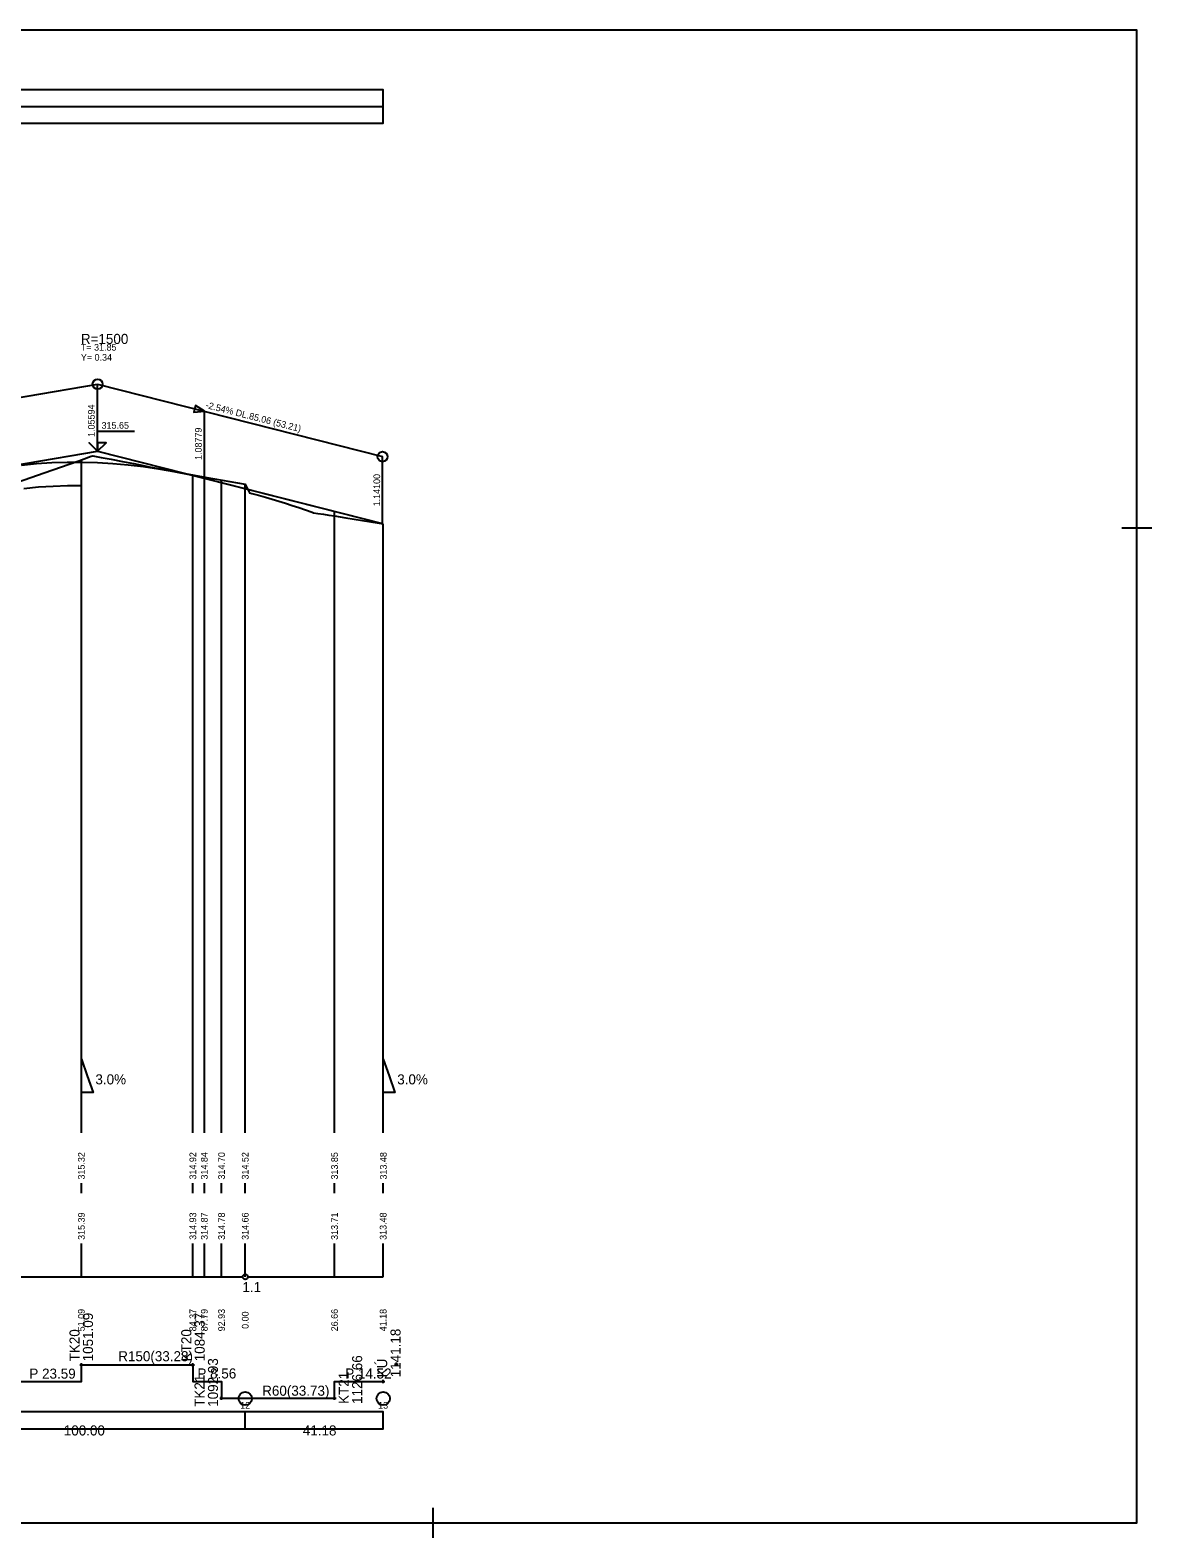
# Model space of a CAD drawing. Extents: x 1301 to 1448, y 183 to 228.
# Drawn here: x 1414.92 to 1448.4, y 182.54 to 227.54 of the extents above; entities that cross this region are included whole.
import ezdxf

# ---------------------------------------------------------------- set-up
doc = ezdxf.new("R2010")
doc.units = 0
for name, color, linetype in [('KOTA', 7, 'Continuous'), ('NOVY_STAV', 7, 'Continuous'), ('NS_OBLOUK', 7, 'Continuous'), ('REZY_PO', 7, 'Continuous'), ('SESTAVY_REZU_PO', 7, 'Continuous'), ('SKLONOVE_POMERY', 7, 'Continuous'), ('SMEROVE_POMERY', 7, 'Continuous'), ('SMEROVE_POMERY_KOD', 7, 'Continuous'), ('SVK_STAT', 7, 'Continuous'), ('TABULKY', 7, 'Continuous'), ('u_drenaz', 7, 'Continuous'), ('u_pricne_rezy', 7, 'Continuous'), ('x_formát_rám', 7, 'Continuous')]:
    doc.layers.add(name, color=color, linetype=linetype)

msp = doc.modelspace()

# ---------------------------------------------------------------- linework, layer by layer
at = {"layer": 'KOTA'}
for points in [[(1416.937, 214.971), (1416.687, 215.221), (1416.937, 214.971), (1416.937, 215.571), (1418.037, 215.571)], [(1416.937, 215.221), (1416.937, 214.971), (1417.187, 215.221), (1416.937, 215.221)], [(1416.937, 214.971), (1417.187, 215.221), (1416.937, 215.221)], [(1416.937, 214.971), (1416.937, 214.971)]]:
    msp.add_lwpolyline(points, dxfattribs=at)
at = {"layer": 'NOVY_STAV'}
for points in [[(1408.521, 215.539), (1416.937, 216.971)], [(1416.937, 214.971), (1416.937, 216.971)], [(1416.937, 216.971), (1425.443, 214.807)], [(1371.343, 199.496), (1372.956, 201.369), (1382.912, 202.588), (1387.709, 206.246), (1394.33, 206.448), (1402.893, 208.614), (1408.521, 213.539), (1416.937, 214.971), (1425.443, 212.807)], [(1425.443, 212.807), (1425.443, 214.807)], [(1414.662, 214.557), (1415.117, 214.6), (1415.572, 214.629), (1416.027, 214.644), (1416.482, 214.646), (1416.937, 214.633), (1417.392, 214.607), (1417.847, 214.567), (1418.302, 214.514), (1418.757, 214.446), (1419.212, 214.365), (1419.667, 214.27), (1420.121, 214.161), (1425.443, 212.807)]]:
    msp.add_lwpolyline(points, dxfattribs=at)
for centre in [(1416.937, 216.971), (1425.443, 214.807)]:
    msp.add_circle(centre, 0.15, dxfattribs=at)
at = {"layer": 'NS_OBLOUK'}
for points in [[(1419.806, 216.138), (1420.122, 216.161), (1419.855, 216.332), (1419.806, 216.138)], [(1420.122, 214.161), (1420.122, 216.161)]]:
    msp.add_lwpolyline(points, dxfattribs=at)
msp.add_lwpolyline([(1420.122, 216.161), (1419.855, 216.332), (1419.806, 216.138)], close=True, dxfattribs=at)
at = {"layer": 'REZY_PO'}
for points in [[(1414.343, 213.98), (1415.343, 214.328), (1416.343, 214.676), (1416.452, 214.714), (1416.452, 214.714), (1416.452, 214.714), (1416.749, 214.818), (1416.789, 214.833), (1417.046, 214.783), (1417.343, 214.728), (1417.676, 214.666), (1418.009, 214.607), (1418.019, 214.605), (1418.343, 214.534), (1418.525, 214.494), (1420.2, 214.181)], [(1420.2, 214.181), (1421.343, 213.984), (1421.343, 213.984), (1421.468, 213.728), (1421.543, 213.709), (1421.743, 213.656), (1421.943, 213.6), (1422.143, 213.541), (1422.343, 213.481), (1422.543, 213.418), (1422.743, 213.353), (1422.943, 213.286), (1423.143, 213.216), (1423.343, 213.145), (1423.383, 213.13), (1423.509, 213.114), (1423.676, 213.09), (1423.842, 213.065), (1424.009, 213.039), (1424.343, 212.985), (1425.343, 212.823), (1425.461, 212.804)]]:
    msp.add_lwpolyline(points, dxfattribs=at)
at = {"layer": 'SESTAVY_REZU_PO'}
for points in [[(1411.418, 190.326), (1421.268, 190.326)], [(1421.418, 190.326), (1425.461, 190.326)]]:
    msp.add_lwpolyline(points, dxfattribs=at)
msp.add_circle((1421.343, 190.326), 0.075, dxfattribs=at)
at = {"layer": 'SKLONOVE_POMERY'}
for points in [[(1416.452, 195.826), (1416.452, 196.826), (1416.452, 196.826), (1416.627, 196.326), (1416.802, 195.826), (1416.452, 195.826)], [(1425.461, 195.826), (1425.461, 196.826), (1425.461, 196.826), (1425.636, 196.326), (1425.811, 195.826), (1425.461, 195.826)]]:
    msp.add_lwpolyline(points, dxfattribs=at)
at = {"layer": 'SMEROVE_POMERY'}
msp.add_lwpolyline([(1414.092, 187.204), (1416.452, 187.204), (1416.452, 187.704), (1419.78, 187.704), (1419.78, 187.204), (1420.636, 187.204), (1420.636, 186.704), (1424.009, 186.704), (1424.009, 187.204), (1425.461, 187.204)], dxfattribs=at)
at = {"layer": 'SMEROVE_POMERY_KOD'}
for points in [[(1416.402, 187.704), (1416.502, 187.704)], [(1416.452, 187.654), (1416.452, 187.754)], [(1419.73, 187.704), (1419.83, 187.704)], [(1419.78, 187.654), (1419.78, 187.754)], [(1425.803, 187.723), (1425.903, 187.723)], [(1425.853, 187.673), (1425.853, 187.773)], [(1425.411, 187.204), (1425.511, 187.204)], [(1425.461, 187.154), (1425.461, 187.254)], [(1420.636, 186.654), (1420.636, 186.754)], [(1424.009, 186.654), (1424.009, 186.754)], [(1420.586, 186.704), (1420.686, 186.704)], [(1423.959, 186.704), (1424.059, 186.704)]]:
    msp.add_lwpolyline(points, dxfattribs=at)
at = {"layer": 'SVK_STAT'}
for points in [[(1416.452, 194.626), (1416.452, 214.714)], [(1419.78, 194.626), (1419.78, 214.26)], [(1420.122, 194.626), (1420.122, 214.196)], [(1420.636, 194.626), (1420.636, 214.106)], [(1421.343, 194.626), (1421.343, 213.984)], [(1424.009, 194.626), (1424.009, 213.172)], [(1425.461, 194.626), (1425.461, 212.804)], [(1416.452, 192.826), (1416.452, 193.126)], [(1419.78, 192.826), (1419.78, 193.126)], [(1420.122, 192.826), (1420.122, 193.126)], [(1420.636, 192.826), (1420.636, 193.126)], [(1421.343, 192.826), (1421.343, 193.126)], [(1424.009, 192.826), (1424.009, 193.126)], [(1425.461, 192.826), (1425.461, 193.126)], [(1416.452, 190.326), (1416.452, 191.326)], [(1419.78, 190.326), (1419.78, 191.326)], [(1420.122, 190.326), (1420.122, 191.326)], [(1420.636, 190.326), (1420.636, 191.326)], [(1421.343, 190.326), (1421.343, 191.326)], [(1424.009, 190.326), (1424.009, 191.326)], [(1425.461, 190.326), (1425.461, 191.326)]]:
    msp.add_lwpolyline(points, dxfattribs=at)
at = {"layer": 'TABULKY'}
for points in [[(1311.343, 224.76), (1425.461, 224.76), (1425.461, 225.76), (1311.343, 225.76), (1311.343, 224.76)], [(1311.343, 225.26), (1425.461, 225.26)]]:
    msp.add_lwpolyline(points, dxfattribs=at)
at = {"layer": 'u_drenaz'}
msp.add_lwpolyline([(1414.739, 213.861), (1415.173, 213.902), (1415.606, 213.929), (1416.04, 213.944), (1416.452, 213.945)], dxfattribs=at)
at = {"layer": 'u_pricne_rezy'}
for points in [[(1311.343, 185.793), (1425.461, 185.793), (1425.461, 186.293), (1311.343, 186.293), (1311.343, 185.793)], [(1421.343, 185.793), (1421.343, 186.293)]]:
    msp.add_lwpolyline(points, dxfattribs=at)
for centre in [(1421.343, 186.693), (1425.461, 186.693)]:
    msp.add_circle(centre, 0.2, dxfattribs=at)
at = {"layer": 'x_formát_rám'}
for p, q in [((1447.504, 212.687), (1448.404, 212.687)), ((1426.954, 182.537), (1426.954, 183.437))]:
    msp.add_line(p, q, dxfattribs=at)
msp.add_lwpolyline([(1300.954, 182.987), (1447.954, 182.987), (1447.954, 227.537), (1300.954, 227.537)], close=True, dxfattribs=at)

# ---------------------------------------------------------------- texts
at = {"layer": 'KOTA'}
msp.add_text('315.65', height=0.2, dxfattribs=at).set_placement((1417.054, 215.64))
at = {"layer": 'NOVY_STAV'}
for s, rotation, p in [(' 1.05594', 90, (1416.849, 215.322)), ('-2.54% DL.85.06 (53.21)', 345.7244, (1420.144, 216.262)), (' 1.14100', 90, (1425.37, 213.249))]:
    msp.add_text(s, height=0.2, rotation=rotation, dxfattribs=at).set_placement(p)
at = {"layer": 'NS_OBLOUK'}
for s, height, p in [('R=1500', 0.3, (1416.437, 218.171)), ('T= 31.85', 0.2, (1416.437, 217.971)), ('Y= 0.34', 0.2, (1416.437, 217.671))]:
    msp.add_text(s, height=height, dxfattribs=at).set_placement(p)
msp.add_text(' 1.08779', height=0.2, rotation=90, dxfattribs=at).set_placement((1420.044, 214.634))
at = {"layer": 'SESTAVY_REZU_PO'}
msp.add_text('1.1', height=0.3, dxfattribs=at).set_placement((1421.259, 189.871))
at = {"layer": 'SKLONOVE_POMERY'}
for p in [(1416.871, 196.071), (1425.88, 196.071)]:
    msp.add_text('3.0%', height=0.3, dxfattribs=at).set_placement(p)
at = {"layer": 'SMEROVE_POMERY'}
for s, p in [('R150(33.28)', (1417.552, 187.808)), ('P 23.59', (1414.899, 187.288)), ('P 8.56', (1419.915, 187.293)), ('P 14.52', (1424.329, 187.291)), ('R60(33.73)', (1421.849, 186.778))]:
    msp.add_text(s, height=0.3, dxfattribs=at).set_placement(p)
at = {"layer": 'SMEROVE_POMERY_KOD'}
for s, p in [('1051.09', (1416.798, 187.804)), ('1084.37', (1420.133, 187.806)), ('TK20', (1416.398, 187.804)), ('KT20', (1419.733, 187.806)), ('1141.18', (1425.979, 187.329)), ('1092.93', (1420.529, 186.448)), ('1126.66', (1424.834, 186.535)), ('KÚ', (1425.579, 187.329)), ('TK21', (1420.129, 186.448)), ('KT21', (1424.434, 186.535))]:
    msp.add_text(s, height=0.3, rotation=90, dxfattribs=at).set_placement(p)
at = {"layer": 'SVK_STAT'}
for s, p in [(' 315.32', (1416.551, 193.156)), (' 314.92', (1419.879, 193.156)), (' 314.84', (1420.221, 193.156)), (' 314.70', (1420.735, 193.156)), (' 314.52', (1421.442, 193.156)), (' 313.85', (1424.108, 193.156)), (' 313.48', (1425.565, 193.156)), (' 315.39', (1416.551, 191.356)), (' 314.93', (1419.879, 191.356)), (' 314.87', (1420.221, 191.356)), (' 314.78', (1420.735, 191.356)), (' 314.66', (1421.442, 191.356)), (' 313.71', (1424.108, 191.356)), (' 313.48', (1425.56, 191.356)), (' 51.09', (1416.551, 188.626)), (' 84.37', (1419.879, 188.626)), (' 87.79', (1420.221, 188.626)), (' 92.93', (1420.735, 188.626)), ('  0.00', (1421.442, 188.626)), (' 26.66', (1424.108, 188.626)), (' 41.18', (1425.56, 188.626))]:
    msp.add_text(s, height=0.2, rotation=90, dxfattribs=at).set_placement(p)
at = {"layer": 'u_pricne_rezy'}
for s, height, p in [('12', 0.2, (1421.192, 186.393)), ('13', 0.2, (1425.31, 186.393)), ('100.00', 0.3, (1415.927, 185.593)), ('41.18', 0.3, (1423.062, 185.593))]:
    msp.add_text(s, height=height, dxfattribs=at).set_placement(p)

doc.saveas('drawing.dxf')
